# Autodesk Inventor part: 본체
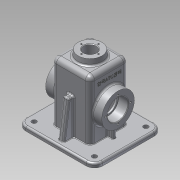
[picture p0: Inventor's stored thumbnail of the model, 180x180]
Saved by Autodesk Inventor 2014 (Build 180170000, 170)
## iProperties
Created: 2016-08
Part Number: 본체
Material: 알루미늄 6061
Document SubType Name: Modeling
Designer: user
Density: 2.71 g/cm^3
Appearance: 알루미늄 - 평지
Mass: 800.285 g
Surface Area: 911.866 cm^2
Volume: 295.308 cm^3
Author: user
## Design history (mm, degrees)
sketch "스케치2"
  geometry: L1 (-51, -52.5)-(51, -52.5); L2 (60, -43.5)-(60, 43.5); L3 (51, 52.5)-(-51, 52.5); L4 (-60, 43.5)-(-60, -43.5); L5 (-60, -52.5)-(60, 52.5); L6 (60, -52.5)-(-60, 52.5); A1 r 9 centre (-51, 43.5) between (-51, 52.5) and (-60, 43.5); A2 r 9 centre (51, 43.5) between (60, 43.5) and (51, 52.5); A3 r 9 centre (-51, -43.5) between (-60, -43.5) and (-51, -52.5); A4 r 9 centre (51, -43.5) between (51, -52.5) and (60, -43.5); 1 further point
  constraints: 12 end point, 8 point on circle, 8 point on line, 8 tangent, 4 centre point, 3 equal radius, 2 midpoint, 2 parallel, 1 horizontal, 1 perpendicular
  dimensions: "d0" = 120 distance of L6.end L5.end; "d1" = 105 distance of L5.end L6.start; "d2" = 9 radius of A1
extrude "돌출1" new body sketch "스케치2" distance "d3" = 3; taper "d4" = 0 deg
sketch "스케치3"
  geometry: L1 (-51, -57.5)-(51, -57.5); L2 (65, -43.5)-(65, 43.5); L3 (51, 57.5)-(-51, 57.5); L4 (-65, 43.5)-(-65, -43.5); L5 (-65, -57.5)-(65, 57.5); L6 (65, -57.5)-(-65, 57.5); A1 r 14 centre (-51, 43.5) between (-51, 57.5) and (-65, 43.5); A2 r 14 centre (51, 43.5) between (65, 43.5) and (51, 57.5); A3 r 14 centre (-51, -43.5) between (-65, -43.5) and (-51, -57.5); A4 r 14 centre (51, -43.5) between (51, -57.5) and (65, -43.5); 1 further point
  constraints: 12 end point, 8 point on circle, 8 point on line, 8 tangent, 4 centre point, 3 equal radius, 2 midpoint, 2 parallel, 1 horizontal, 1 perpendicular
  dimensions: "d5" = 130 distance of L6.end L5.end; "d6" = 115 distance of L5.end L6.start; "d7" = 14 radius of A1
extrude "돌출2" join sketch "스케치3" distance "d8" = 7; taper "d9" = 0 deg
sketch "스케치4"
  geometry: L1 (32.5, 0)-(-32.5, 0); L2 (-32.5, 0)-(-32.5, 110); L3 (-32.5, 110)-(32.5, 110); L4 (32.5, 110)-(32.5, 0); L5 (51, 0)-(-51, 0) reference; L6 (71.4, 0)-(-71.4, 0) reference; L7 (0, -22)-(0, 132) reference; 1 further point
  constraints: 8 end point, 2 parallel, 1 collinear, 1 horizontal, 1 perpendicular, 1 other
  dimensions: "d10" = 65 distance of L2.end L3.end; "d11" = 110 distance of L1.end L2.end
extrude "돌출3" join sketch "스케치4" stored distance "d12" = 65; taper "d13" = 0 deg
fillet "모깎기1" dims "d14" = 8
sketch "스케치5"
  geometry: L1 (47.5, 82.5)-(-47.5, 82.5); L2 (-47.5, 82.5)-(-47.5, 55); L3 (-47.5, 55)-(47.5, 55); L4 (47.5, 55)-(47.5, 82.5); L5 (66.5, 0)-(-66.5, 0) reference; L6 (0, -20.4)-(0, 122.4) reference; 1 further point
  constraints: 8 end point, 2 parallel, 1 horizontal, 1 perpendicular, 1 other
  dimensions: "d15" = 27.5 distance of L3.end L1.start; "d16" = 95 distance of L1.start L1.end; "d17" = 55 distance between parallel lines of L5 L3
revolve "회전1" sketch "스케치5" stored, may be unused: angle "d18" = 90 deg
fillet "모깎기5" dims "d83" = 3
sketch "스케치6"
  geometry: L1 (24.5, 110)-(-24.5, 110) reference; L2 (0, 110)-(0, 120); L3 (0, 120)-(-20, 120); L4 (-20, 120)-(-21.228, 110); L5 (0, 110)-(-21.228, 110); L6 (-32.5, 102)-(-32.5, 67.49) reference; 1 further point
  constraints: 8 end point, 2 perpendicular, 1 midpoint, 1 parallel, 1 point on line
  dimensions: "d19" = 7 deg angle of L6 L4; "d20" = 40 diameter of L3.end L2; "d21" = 10 distance of L2.start L2.end
revolve "회전2" sketch "스케치6" stored, may be unused: angle "d22" = 90 deg
sketch "스케치7"
  geometry: L1 (-32.5, 10)-(-32.5, 102) reference; L2 (43.5, 10)-(-43.5, 10) reference; L3 (-43.5, 10)-(-57.5, 10) reference; L4 (-32.5, 70)-(-41.068, 70); L5 (-41.068, 70)-(-49.5, 10); L6 (-57.5, 3)-(-57.5, 10) reference; L7 (-52.5, 0)-(-43.5, 0) reference; 1 further point
  constraints: 4 end point, 2 point on line, 1 parallel
  dimensions: "d23" = 8 deg angle of L6 L5; "d24" = 70 distance from line of L7 L4.end; "d25" = 8 distance of L3.end L5.end
extrude "돌출4" join sketch "스케치7" stored distance "d26" = 10; taper "d27" = 0 deg
sketch "스케치8"
  geometry: L1 (-42.5, 10)-(42.5, 10); L2 (32.5, 27.5)-(47.5, 27.5) reference; L3 (-47.5, 27.5)-(-32.5, 27.5) reference; L4 (-51, 10)-(51, 10) reference; L5 (32.5, 10)-(32.5, 42.51) reference; L6 (-32.5, 42.51)-(-32.5, 10) reference; L7 (42.5, 10)-(42.5, 55); L8 (42.5, 55)-(-42.5, 55); L9 (-42.5, 55)-(-42.5, 10); L10 (47.5, 27.5)-(47.5, 82.5) reference; 2 further points
  constraints: 8 end point, 2 perpendicular, 1 collinear, 1 midpoint, 1 parallel, 1 point on line
  dimensions: "d84" = 10 distance between parallel lines of L7 L5; "d85" = 10 distance between parallel lines of L9 L6
extrude "돌출5" join sketch "스케치8" stored distance "d30" = 6; taper "d31" = 0 deg
node "작업 평면1"
sketch "스케치9"
  geometry: L1 (0, -8)-(92, -8) reference; L2 (-18, 44.5)-(-18, 4.5) reference; 2 further points
  constraints: 1 other
  dimensions: "d33" = 32.5 distance from line of L1 point (8, 24.5); "d34" = 26 distance from line of point (8, 24.5) L2
feature "엠보싱1" sketch "스케치9" dims "d5" = 130, "d6" = 115, "d7" = 14, "d35" = 0.5, "d36" = 0
sketch "스케치10"
  geometry: L1 (55, -80.5)-(55, 80.5) reference; L2 (77, 0)-(-77, 0) reference; L3 (0, -21)-(0, 21); C1 r 27.5 at (0, 0) reference; A1 r 21 centre (0, 0) between (0, -21) and (0, 21); 5 further points
  constraints: 4 point on circle, 2 coincident, 2 end point, 2 midpoint, 2 point on line, 1 centre point, 1 concentric, 1 perpendicular
  dimensions: "d37" = 42 diameter of A1
hole "구멍1" sketch "스케치10" at (-21, 0), (0, -21), (21, 0), (0, 21) diameter "d38" = 3.242; stored, may be unused: countersink angle "d42" = 90 deg, drill point angle "d44" = 118 deg; dims "d39" = 8, "d40" = 4, "d41" = 2, "d43" = 10
sketch "스케치11"
  geometry: L1 (-91, 0)-(91, 0) reference; L2 (0, -80.5)-(0, 80.5) reference; A1 r 14.5 centre (0, 0) between (0, 14.5) and (0, -14.5); 3 further points
  constraints: 4 point on circle, 4 point on line, 1 centre point, 1 coincident
  dimensions: "d45" = 29 diameter of A1
hole "구멍2" sketch "스케치11" at (0, 14.5), (0, -14.5), (-14.5, 0), (14.5, 0) diameter "d46" = 2.459; stored, may be unused: countersink angle "d50" = 90 deg, drill point angle "d52" = 118 deg; dims "d47" = 7, "d48" = 4, "d49" = 2, "d51" = 9
sketch "스케치12"
  geometry: L1 (47.5, 27.5)-(47.5, 82.5) reference; L2 (-47.5, 27.5)-(-47.5, 82.5) reference; L3 (47.5, 55)-(-47.5, 55); L4 (47.5, 55)-(47.5, 72.5); L5 (47.5, 72.5)-(30.5, 72.5); L6 (30.5, 72.5)-(30.5, 70); L7 (30.5, 70)-(-30.5, 70); L8 (-30.5, 70)-(-30.5, 72.5); L9 (-30.5, 72.5)-(-47.5, 72.5); L10 (-47.5, 55)-(-47.5, 72.5); 1 further point
  constraints: 16 end point, 3 perpendicular, 2 midpoint, 2 parallel, 2 point on line, 1 collinear
  dimensions: "d53" = 35 diameter of L5 L3; "d54" = 35 diameter of L9 L3; "d55" = 30 diameter of L7 L3; "d56" = 17 distance of L4.end L5.end; "d57" = 17 distance of L8.end L9.end
revolve "회전3" sketch "스케치12" stored, may be unused: angle "d58" = 90 deg
sketch "스케치13"
  geometry: L1 (51, 0)-(-51, 0) reference; L2 (27.5, 105)-(-27.5, 105); L3 (-27.5, 105)-(-27.5, 0); L4 (-27.5, 0)-(27.5, 0); L5 (27.5, 0)-(27.5, 105); L6 (27.5, 105)-(-27.5, 0); L7 (-27.5, 105)-(27.5, 0); L8 (91, 0)-(-91, 0) reference; L9 (0, -24)-(0, 144) reference; L10 (-32.5, 102)-(-32.5, 67.49) reference; L11 (24.5, 110)-(-24.5, 110) reference; 3 further points
  constraints: 12 end point, 3 midpoint, 2 parallel, 1 collinear, 1 horizontal, 1 perpendicular, 1 point on line
  dimensions: "d59" = 5 distance between parallel lines of L10 L3; "d60" = 5 distance between parallel lines of L11 L2
extrude "돌출6" cut sketch "스케치13" stored distance "d61" = 55; taper "d62" = 0 deg
fillet "모깎기2" dims "d63" = 3
chamfer "모따기1" distance "d64" = 1; stored, may be unused: second distance "d65" = 2, angle "d66" = 45 deg
fillet "모깎기3" dims "d67" = 0.3
hole "구멍3" diameter "d70" = 21; stored, may be unused: countersink angle "d74" = 90 deg, drill point angle "d76" = 118 deg; dims "d71" = 21, "d72" = 4, "d73" = 2, "d75" = 9, "d77" = 10, "d78" = 10
chamfer "모따기2" distance "d79" = 1; stored, may be unused: second distance "d80" = 2, angle "d81" = 45 deg
fillet "모깎기4" dims "d82" = 3
fillet "모깎기9" dims "d89" = 3
fillet "모깎기12" dims "d92" = 1
sketch "스케치14"
  geometry: L1 (91, 0)-(-91, 0) reference; L2 (0, -80.5)-(0, 80.5) reference; 5 further points
  constraints: 2 horizontal alignment, 2 symmetric about line, 2 vertical alignment
  dimensions: "d93" = 87 distance of point (-51, 43.5) point (-51, -43.5); "d94" = 102 distance of point (51, 43.5) point (-51, 43.5)
hole "구멍4" sketch "스케치14" at (-51, -43.5), (-51, 43.5), (51, 43.5), (51, -43.5) diameter "d95" = 8; stored, may be unused: countersink angle "d99" = 90 deg, drill point angle "d101" = 118 deg; dims "d96" = 21, "d97" = 4, "d98" = 2, "d100" = 9
fillet "모깎기13" dims "d102" = 3
fillet "모깎기15" dims "d104" = 3
fillet "모깎기16" dims "d105" = 3
fillet "모깎기17" dims "d106" = 3
fillet "모깎기18" dims "d107" = 3
fillet "모깎기19" dims "d108" = 3
node "솔리드1"
mirror "대칭1"
mirror "대칭2"
node "투영된 루프1"
other parameters: "d32" = 29
